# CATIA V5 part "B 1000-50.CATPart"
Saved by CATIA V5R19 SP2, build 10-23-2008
Part number: B 1000-50
Bounding box of the stored display mesh (mm): x -24.865 to 24.865, y -24.997 to 24.997, z 0 to 195
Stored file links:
  C:\Users\Bora\Desktop\3D Katı model\B serisi\B 1000\B 1000-50.CATPart
  C:\Program Files\Dassault Systemes\B19\intel_a\reffiles\standard\MetricThinPitch.txt
  C:\Program Files\Dassault Systemes\B19\intel_a\reffiles\standard\MetricThickPitch.txt
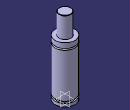
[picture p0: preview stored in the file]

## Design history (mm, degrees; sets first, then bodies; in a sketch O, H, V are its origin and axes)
Body1 (main body)
  Sketch1 on yz-plane, origin (0, 0, 0), H (0, 1, 0), V (0, 0, 1)
    point P3 (15, 194)
    point P5 (15, 194)
    point P10 (25, 125.5)
    point P11 (25, 129.5)
    point P13 (25, 129.5)
    point P14 (25, 125.5)
    line L1 (25, 0) -> (25, 8)
    line L2 (15, 194) -> (15, 142)
    arc A1 centre (14, 194) radius 1 from (15, 194) to (14, 195) ccw
    line L3 (21.5, 13) -> (21.5, 8)
    line L4 (25, 13) -> (25, 125.5)
    line L5 (25, 129.5) -> (25, 142)
    arc A2 centre (25, 127.5) radius 2 from (25, 129.5) to (25, 125.5) ccw
    line L6 (14, 195) -> (0, 195)
    point P15 (0, 195)
    line L7 (15, 142) -> (25, 142)
    line L8 (0, 0) -> (25, 0)
    line L9 (21.5, 13) -> (25, 13)
    line L10 (21.5, 8) -> (25, 8)
    coincidence: P15 V, P3 P5, P10 P14, P11 P13
    tangency: L6 A1
    horizontal: L7 H, L8 H, L9 H, L10 H
  Shaft1: profile Sketch1, axis Sketch1.V, angle 360
  Sketch2 on face of Shaft1 from Sketch1.L8, origin (0, 0, 0), H (1, 0, 0), V (0, -1, 0)
    point P1 (10, 0)
    distance P1 V = 10
  Hole1: placed by Sketch2, at (10, 0, 0) direction (0, 0, 1), diameter 6.647, depth 13, threaded "M8", thread diameter 8, thread depth 13, pitch 1.25
  CircPattern1: of Hole1, instances 2, angular step 180, axis from xy-plane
